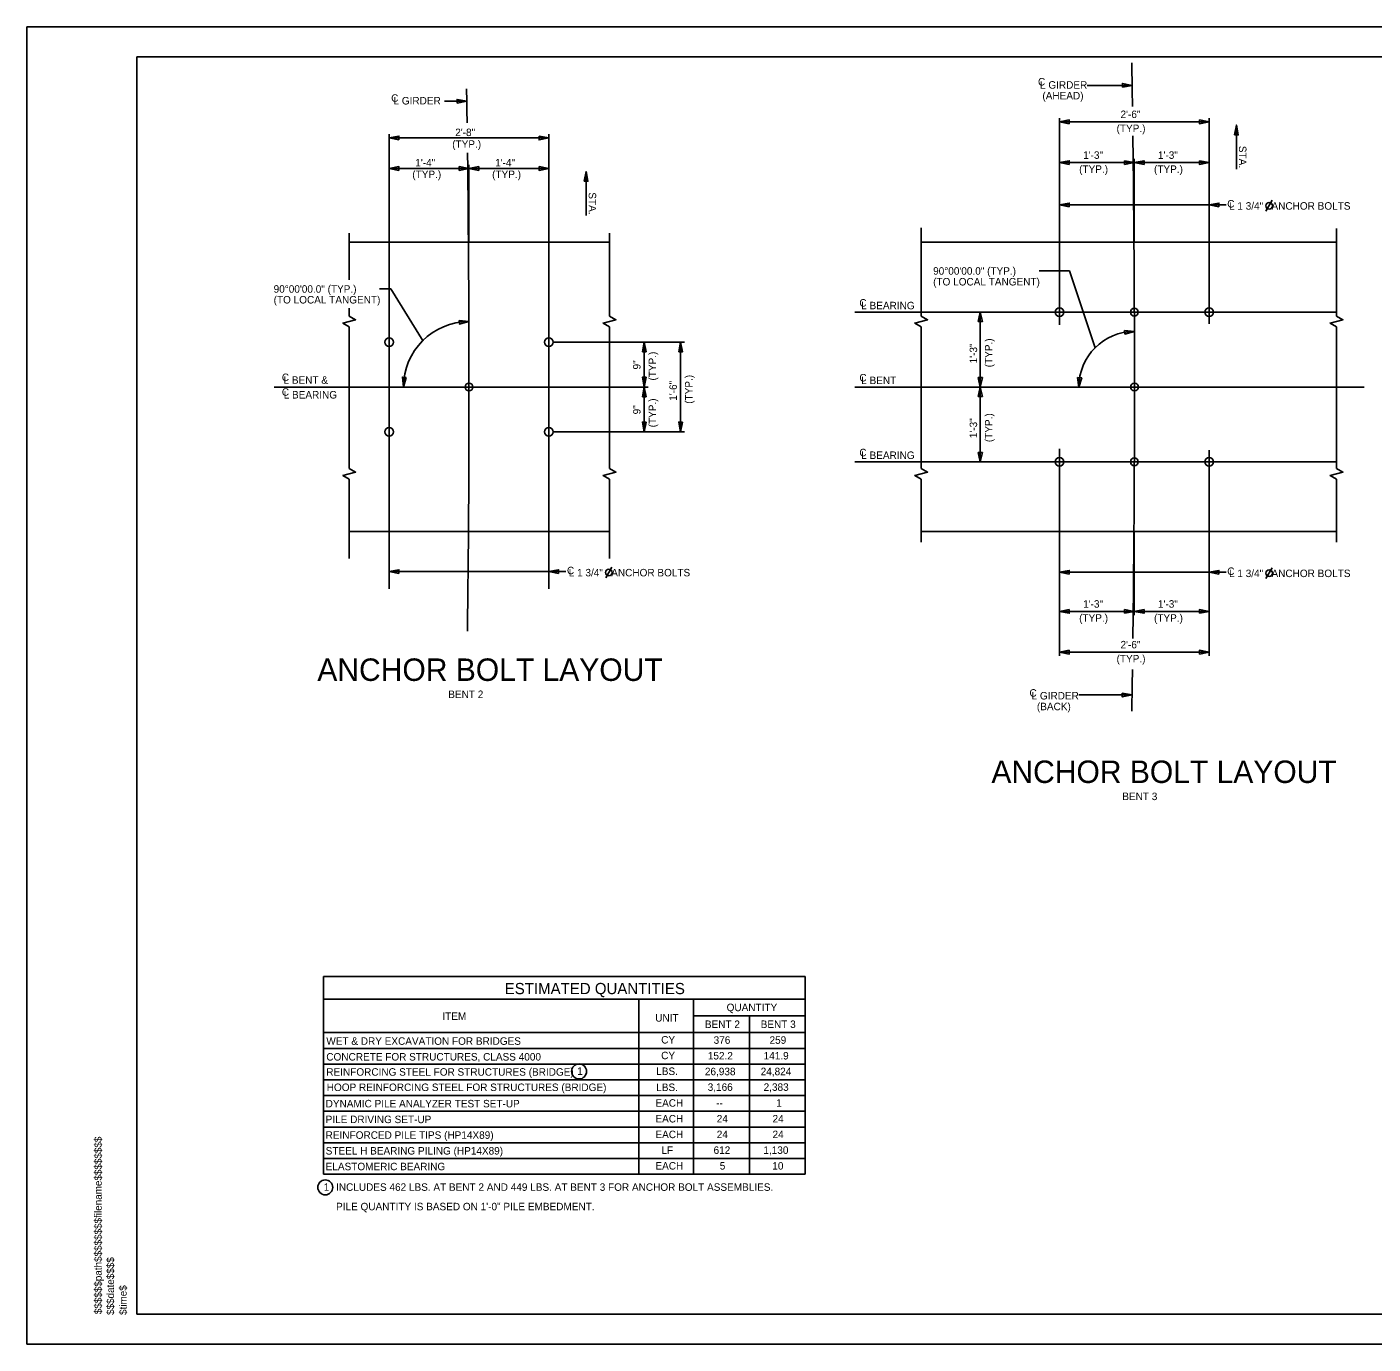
# Model space of a CAD drawing. Extents: x 1970675.2 to 1970711.3, y 796145.2 to 796167.2.
# Drawn here: x 1970675.24 to 1970697.72, y 796145.25 to 796167.25 of the extents above; entities that cross this region are included whole.
import ezdxf

# ---------------------------------------------------------------- set-up
doc = ezdxf.new("R2010")
doc.units = 0
for name, color, linetype in [('BR_AUTO DIMENSION', 7, 'Continuous'), ('BR_BORDER LINES', 7, 'Continuous'), ('BR_CENTER LINES', 7, 'Continuous'), ('BR_CONCRETE', 7, 'Continuous'), ('BR_STRUCTURAL STEEL', 7, 'Continuous'), ('BR_TEXT', 7, 'Continuous'), ('Default', 7, 'Continuous'), ('Level 31', 7, 'Continuous'), ('RD_SHT_ID', 7, 'Continuous')]:
    doc.layers.add(name, color=color, linetype=linetype)

msp = doc.modelspace()

# ---------------------------------------------------------------- linework, layer by layer
at = {"layer": 'BR_AUTO DIMENSION'}
for p, q in [((1970692.947, 796166.27), (1970693.696, 796166.27)), ((1970682.211, 796166.005), (1970682.584, 796166.005)), ((1970692.482, 796164.614), (1970692.482, 796165.724)), ((1970692.482, 796165.661), (1970694.982, 796165.661)), ((1970694.982, 796164.614), (1970694.982, 796165.724)), ((1970681.287, 796163.711), (1970681.287, 796165.454)), ((1970683.954, 796163.711), (1970683.954, 796165.454)), ((1970681.287, 796165.392), (1970683.954, 796165.392)), ((1970692.482, 796164.981), (1970693.732, 796164.981)), ((1970693.732, 796163.649), (1970693.732, 796165.043)), ((1970693.732, 796164.981), (1970694.982, 796164.981)), ((1970681.287, 796164.882), (1970682.62, 796164.882)), ((1970682.62, 796163.711), (1970682.62, 796164.944)), ((1970682.62, 796163.649), (1970682.62, 796164.944)), ((1970683.954, 796164.882), (1970682.62, 796164.882)), ((1970695.264, 796164.274), (1970692.482, 796164.274)), ((1970692.143, 796163.173), (1970692.649, 796163.173)), ((1970693.078, 796161.888), (1970692.649, 796163.173)), ((1970681.127, 796162.872), (1970681.316, 796162.872)), ((1970681.856, 796162), (1970681.316, 796162.872)), ((1970691.158, 796161.232), (1970691.158, 796162.482)), ((1970684.016, 796161.982), (1970686.217, 796161.982)), ((1970685.548, 796161.982), (1970685.548, 796161.232)), ((1970686.154, 796161.982), (1970686.154, 796160.482)), ((1970684.016, 796161.232), (1970685.61, 796161.232)), ((1970685.548, 796161.232), (1970685.548, 796160.482)), ((1970691.158, 796159.982), (1970691.158, 796161.232)), ((1970684.016, 796160.482), (1970686.217, 796160.482)), ((1970693.732, 796158.816), (1970693.732, 796157.421)), ((1970684.236, 796158.148), (1970681.287, 796158.148)), ((1970695.264, 796158.137), (1970692.482, 796158.137)), ((1970692.482, 796157.85), (1970692.482, 796156.741)), ((1970694.982, 796157.85), (1970694.982, 796156.741)), ((1970692.482, 796157.484), (1970693.732, 796157.484)), ((1970693.732, 796157.484), (1970694.982, 796157.484)), ((1970692.482, 796156.804), (1970694.982, 796156.804)), ((1970693.694, 796156.089), (1970692.808, 796156.089)), ((1970680.189, 796151.385), (1970688.235, 796151.385)), ((1970680.189, 796148.084), (1970680.189, 796151.385)), ((1970688.235, 796148.084), (1970688.235, 796151.385)), ((1970680.189, 796151.01), (1970688.235, 796151.01)), ((1970685.454, 796148.084), (1970685.454, 796151.01)), ((1970686.371, 796148.084), (1970686.371, 796151.01)), ((1970686.371, 796150.729), (1970688.235, 796150.729)), ((1970687.303, 796148.084), (1970687.303, 796150.729)), ((1970680.189, 796150.448), (1970688.235, 796150.448)), ((1970680.189, 796150.185), (1970688.235, 796150.185)), ((1970680.189, 796149.923), (1970688.235, 796149.923)), ((1970680.189, 796149.662), (1970688.235, 796149.662)), ((1970680.189, 796149.396), (1970688.235, 796149.396)), ((1970680.189, 796149.134), (1970688.235, 796149.134)), ((1970680.189, 796148.871), (1970688.235, 796148.871)), ((1970680.189, 796148.609), (1970688.235, 796148.609)), ((1970680.189, 796148.346), (1970688.235, 796148.346)), ((1970680.189, 796148.084), (1970688.235, 796148.084))]:
    msp.add_line(p, q, dxfattribs=at)
for points in [[(1970693.534, 796166.239), (1970693.696, 796166.27), (1970693.534, 796166.302)], [(1970682.421, 796165.974), (1970682.584, 796166.005), (1970682.421, 796166.036)], [(1970692.645, 796165.63), (1970692.482, 796165.661), (1970692.645, 796165.692)], [(1970694.82, 796165.692), (1970694.982, 796165.661), (1970694.82, 796165.63)], [(1970681.45, 796165.36), (1970681.287, 796165.392), (1970681.45, 796165.423)], [(1970683.791, 796165.423), (1970683.954, 796165.392), (1970683.791, 796165.36)], [(1970695.405, 796165.443), (1970695.437, 796165.606), (1970695.468, 796165.443)], [(1970692.645, 796164.949), (1970692.482, 796164.981), (1970692.645, 796165.012)], [(1970693.57, 796165.012), (1970693.732, 796164.981), (1970693.57, 796164.949)], [(1970693.895, 796164.949), (1970693.732, 796164.981), (1970693.895, 796165.012)], [(1970694.82, 796165.012), (1970694.982, 796164.981), (1970694.82, 796164.949)], [(1970681.45, 796164.85), (1970681.287, 796164.882), (1970681.45, 796164.913)], [(1970682.458, 796164.913), (1970682.62, 796164.882), (1970682.458, 796164.85)], [(1970682.783, 796164.85), (1970682.62, 796164.882), (1970682.783, 796164.913)], [(1970683.791, 796164.913), (1970683.954, 796164.882), (1970683.791, 796164.85)], [(1970684.544, 796164.668), (1970684.576, 796164.831), (1970684.607, 796164.668)], [(1970692.645, 796164.242), (1970692.482, 796164.274), (1970692.645, 796164.305)], [(1970695.145, 796164.242), (1970694.982, 796164.274), (1970695.145, 796164.305)], [(1970682.454, 796162.344), (1970682.619, 796162.326), (1970682.459, 796162.282)], [(1970691.122, 796162.326), (1970691.158, 796162.482), (1970691.194, 796162.326)], [(1970693.569, 796162.178), (1970693.733, 796162.161), (1970693.574, 796162.115)], [(1970685.516, 796161.82), (1970685.548, 796161.982), (1970685.579, 796161.82)], [(1970686.123, 796161.82), (1970686.154, 796161.982), (1970686.186, 796161.82)], [(1970681.57, 796161.392), (1970681.526, 796161.232), (1970681.507, 796161.397)], [(1970685.579, 796161.395), (1970685.548, 796161.232), (1970685.516, 796161.395)], [(1970691.122, 796161.388), (1970691.158, 796161.232), (1970691.194, 796161.388)], [(1970692.783, 796161.391), (1970692.806, 796161.232), (1970692.855, 796161.385)], [(1970685.516, 796161.07), (1970685.548, 796161.232), (1970685.579, 796161.07)], [(1970691.122, 796161.076), (1970691.158, 796161.232), (1970691.194, 796161.076)], [(1970685.579, 796160.645), (1970685.548, 796160.482), (1970685.516, 796160.645)], [(1970686.186, 796160.645), (1970686.154, 796160.482), (1970686.123, 796160.645)], [(1970691.122, 796160.138), (1970691.158, 796159.982), (1970691.194, 796160.138)], [(1970681.45, 796158.117), (1970681.287, 796158.148), (1970681.45, 796158.18)], [(1970684.116, 796158.117), (1970683.954, 796158.148), (1970684.116, 796158.18)], [(1970692.645, 796158.105), (1970692.482, 796158.137), (1970692.645, 796158.168)], [(1970695.145, 796158.105), (1970694.982, 796158.137), (1970695.145, 796158.168)], [(1970692.645, 796157.515), (1970692.482, 796157.484), (1970692.645, 796157.453)], [(1970693.57, 796157.453), (1970693.732, 796157.484), (1970693.57, 796157.515)], [(1970693.895, 796157.515), (1970693.732, 796157.484), (1970693.895, 796157.453)], [(1970694.82, 796157.453), (1970694.982, 796157.484), (1970694.82, 796157.515)], [(1970692.645, 796156.835), (1970692.482, 796156.804), (1970692.645, 796156.772)], [(1970694.82, 796156.772), (1970694.982, 796156.804), (1970694.82, 796156.835)], [(1970693.532, 796156.12), (1970693.694, 796156.089), (1970693.532, 796156.057)]]:
    msp.add_lwpolyline(points, close=True, dxfattribs=at)
for centre in [(1970693.732, 796162.482), (1970682.62, 796161.232), (1970693.735, 796161.232), (1970693.732, 796159.982)]:
    msp.add_circle(centre, 0.0652, dxfattribs=at)
for centre, radius, start in [((1970682.62, 796161.232), 1.094, 90.1013), ((1970693.735, 796161.232), 0.929, 90.081)]:
    msp.add_arc(centre, radius, start, 180, dxfattribs=at)
at = {"layer": 'BR_BORDER LINES'}
for p, q in [((1970710.736, 796166.746), (1970677.07, 796166.746)), ((1970677.07, 796145.746), (1970677.07, 796166.746)), ((1970677.07, 796145.746), (1970710.736, 796145.746))]:
    msp.add_line(p, q, dxfattribs=at)
at = {"layer": 'BR_CENTER LINES'}
for p, q in [((1970692.482, 796162.268), (1970692.482, 796164.614)), ((1970694.982, 796162.286), (1970694.982, 796164.614)), ((1970681.287, 796157.861), (1970681.287, 796164.082)), ((1970683.954, 796157.861), (1970683.954, 796163.98)), ((1970697.111, 796162.482), (1970689.064, 796162.482)), ((1970684.968, 796161.232), (1970679.364, 796161.232)), ((1970697.57, 796161.232), (1970689.064, 796161.232)), ((1970692.482, 796160.197), (1970692.482, 796157.85)), ((1970694.982, 796160.178), (1970694.982, 796157.85)), ((1970697.111, 796159.982), (1970689.064, 796159.982))]:
    msp.add_line(p, q, dxfattribs=at)
for centre, radius, start, end in [((1970365.235, 796161.232), 328.5, 0.81737, 0.9448), ((1970373.12, 796161.232), 309.5, 0.81693, 0.92238), ((1970365.235, 796161.232), 328.5, 360, 0.73157), ((1970373.12, 796161.232), 309.5, 359.24506, 0.72377), ((1970365.235, 796161.232), 328.5, 359.26762, 360), ((1970365.235, 796161.232), 328.5, 359.0552, 359.17682)]:
    msp.add_arc(centre, radius, start, end, dxfattribs=at)
at = {"layer": 'BR_CONCRETE'}
for p, q in [((1970684.968, 796163.649), (1970680.621, 796163.649)), ((1970697.111, 796163.649), (1970690.173, 796163.649)), ((1970690.173, 796161.232), (1970697.111, 796161.232)), ((1970684.968, 796158.816), (1970680.621, 796158.816)), ((1970697.111, 796158.816), (1970690.173, 796158.816))]:
    msp.add_line(p, q, dxfattribs=at)
at = {"layer": 'BR_STRUCTURAL STEEL'}
for centre, radius in [((1970692.482, 796162.482), 0.073), ((1970694.982, 796162.482), 0.073), ((1970681.287, 796161.982), 0.073), ((1970683.954, 796161.982), 0.0729), ((1970681.287, 796160.482), 0.073), ((1970683.954, 796160.482), 0.073), ((1970692.482, 796159.982), 0.073), ((1970694.982, 796159.982), 0.073)]:
    msp.add_circle(centre, radius, dxfattribs=at)
at = {"layer": 'BR_TEXT'}
for p, q in [((1970695.437, 796164.873), (1970695.437, 796165.606)), ((1970684.576, 796164.098), (1970684.576, 796164.831)), ((1970695.931, 796164.169), (1970696.036, 796164.35)), ((1970684.903, 796158.043), (1970685.008, 796158.225)), ((1970695.931, 796158.032), (1970696.036, 796158.213))]:
    msp.add_line(p, q, dxfattribs=at)
for centre, radius in [((1970695.984, 796164.259), 0.055), ((1970684.955, 796158.134), 0.055), ((1970695.984, 796158.122), 0.055), ((1970684.459, 796149.8), 0.125), ((1970680.219, 796147.864), 0.125)]:
    msp.add_circle(centre, radius, dxfattribs=at)
at = {"layer": 'Default'}
for p, q in [((1970690.173, 796163.888), (1970690.173, 796162.417)), ((1970697.111, 796163.878), (1970697.111, 796162.417)), ((1970680.621, 796163.803), (1970680.621, 796163.023)), ((1970684.968, 796163.803), (1970684.968, 796162.417)), ((1970680.621, 796162.547), (1970680.621, 796162.417)), ((1970680.621, 796162.239), (1970680.621, 796161.232)), ((1970684.968, 796162.239), (1970684.968, 796161.232)), ((1970690.173, 796162.239), (1970690.173, 796161.232)), ((1970697.111, 796162.239), (1970697.111, 796161.232)), ((1970680.621, 796161.232), (1970680.621, 796159.871)), ((1970684.968, 796161.232), (1970684.968, 796159.871)), ((1970690.173, 796161.232), (1970690.173, 796159.871)), ((1970697.111, 796161.232), (1970697.111, 796159.871)), ((1970680.621, 796159.693), (1970680.621, 796158.366)), ((1970684.968, 796159.693), (1970684.968, 796158.366)), ((1970690.173, 796159.693), (1970690.173, 796158.639)), ((1970697.111, 796159.693), (1970697.111, 796158.639))]:
    msp.add_line(p, q, dxfattribs=at)
for points in [[(1970680.621, 796162.239), (1970680.513, 796162.301), (1970680.726, 796162.356), (1970680.621, 796162.417)], [(1970684.968, 796162.239), (1970684.86, 796162.301), (1970685.073, 796162.356), (1970684.968, 796162.417)], [(1970690.173, 796162.239), (1970690.065, 796162.301), (1970690.278, 796162.356), (1970690.173, 796162.417)], [(1970697.111, 796162.239), (1970697.003, 796162.301), (1970697.216, 796162.356), (1970697.111, 796162.417)], [(1970680.621, 796159.693), (1970680.513, 796159.755), (1970680.726, 796159.81), (1970680.621, 796159.871)], [(1970684.968, 796159.693), (1970684.86, 796159.755), (1970685.073, 796159.81), (1970684.968, 796159.871)], [(1970690.173, 796159.693), (1970690.065, 796159.755), (1970690.278, 796159.81), (1970690.173, 796159.871)], [(1970697.111, 796159.693), (1970697.003, 796159.755), (1970697.216, 796159.81), (1970697.111, 796159.871)]]:
    msp.add_lwpolyline(points, dxfattribs=at)
at = {"layer": 'Level 31'}
msp.add_line((1970711.236, 796167.246), (1970675.236, 796167.246), dxfattribs=at)
msp.add_lwpolyline([(1970675.236, 796167.246), (1970675.236, 796145.246), (1970711.236, 796145.246), (1970711.236, 796167.246)], dxfattribs=at)

# ---------------------------------------------------------------- texts
at = {"layer": 'BR_AUTO DIMENSION'}
for s, rotation, p in [('C', 360, (1970692.123, 796166.268)), ('L GIRDER', 360, (1970692.157, 796166.215)), ('C', 360, (1970681.32, 796165.996)), ('(AHEAD)', 360, (1970692.197, 796166.035)), ('L GIRDER', 360, (1970681.359, 796165.951)), ('STA.', 270, (1970695.48, 796165.259)), ('STA.', 270, (1970684.619, 796164.484)), ('C', 360, (1970695.284, 796164.23)), ('L 1 3/4"   ANCHOR BOLTS', 360, (1970695.314, 796164.194)), ('C', 360, (1970689.14, 796162.575)), ('L BEARING', 360, (1970689.171, 796162.53)), ('9"', 90, (1970685.485, 796161.525)), ('(TYP.)', 90, (1970685.746, 796161.34)), ('C', 360, (1970679.494, 796161.331)), ('L BENT &', 360, (1970679.522, 796161.286)), ('(TYP.)', 90, (1970686.353, 796160.952)), ('C', 360, (1970689.14, 796161.325)), ('L BENT', 360, (1970689.171, 796161.28)), ('C', 360, (1970679.494, 796161.086)), ('L BEARING', 360, (1970679.525, 796161.04)), ('1\'-6"', 90, (1970686.092, 796161.002)), ('9"', 90, (1970685.485, 796160.775)), ('(TYP.)', 90, (1970685.746, 796160.558)), ('C', 360, (1970689.14, 796160.075)), ('L BEARING', 360, (1970689.171, 796160.03)), ('C', 360, (1970684.256, 796158.105)), ('C', 360, (1970695.284, 796158.093)), ('L 1 3/4"   ANCHOR BOLTS', 360, (1970684.286, 796158.069)), ('L 1 3/4"   ANCHOR BOLTS', 360, (1970695.314, 796158.057)), ('BENT 2', 360, (1970682.274, 796156.037)), ('C', 360, (1970691.981, 796156.06)), ('L GIRDER', 360, (1970692.016, 796156.013)), ('(BACK)', 360, (1970692.105, 796155.833)), ('BENT 3', 360, (1970693.532, 796154.332))]:
    msp.add_text(s, height=0.125, rotation=rotation, dxfattribs=at).set_placement(p)
for s, p in [('2\'-6"', (1970693.502, 796165.724)), ('2\'-8"', (1970682.39, 796165.423)), ('(TYP.)', (1970693.436, 796165.489)), ('(TYP.)', (1970682.34, 796165.227)), ('1\'-4"', (1970681.723, 796164.916)), ('1\'-4"', (1970683.056, 796164.916)), ('1\'-3"', (1970692.877, 796165.043)), ('1\'-3"', (1970694.127, 796165.043)), ('(TYP.)', (1970681.673, 796164.722)), ('(TYP.)', (1970683.006, 796164.722)), ('(TYP.)', (1970692.811, 796164.809)), ('(TYP.)', (1970694.061, 796164.809)), ('90%%D00\'00.0" (TYP.)', (1970690.372, 796163.108)), ('(TO LOCAL TANGENT)', (1970690.372, 796162.928)), ('90%%D00\'00.0" (TYP.)', (1970679.357, 796162.807)), ('(TO LOCAL TANGENT)', (1970679.357, 796162.627)), ('1\'-3"', (1970692.877, 796157.546)), ('1\'-3"', (1970694.127, 796157.546)), ('(TYP.)', (1970692.811, 796157.312)), ('(TYP.)', (1970694.061, 796157.312)), ('2\'-6"', (1970693.502, 796156.866)), ('(TYP.)', (1970693.436, 796156.631))]:
    msp.add_text(s, height=0.125, dxfattribs=at).set_placement(p)
at = {"layer": 'BR_TEXT'}
for s, height, rotation, p in [('1\'-3"', 0.125, 90, (1970691.107, 796161.627)), ('(TYP.)', 0.125, 90, (1970691.363, 796161.561)), ('1\'-3"', 0.125, 90, (1970691.107, 796160.377)), ('(TYP.)', 0.125, 90, (1970691.363, 796160.311)), ('ANCHOR BOLT LAYOUT', 0.375, 360, (1970680.087, 796156.323)), ('ANCHOR BOLT LAYOUT', 0.375, 360, (1970691.345, 796154.618)), ('ESTIMATED QUANTITIES', 0.1875, 0, (1970683.217, 796151.091)), ('QUANTITY', 0.125, 0, (1970686.923, 796150.807)), ('ITEM', 0.125, 0, (1970682.176, 796150.661)), ('UNIT', 0.125, 0, (1970685.73, 796150.632)), ('BENT 2', 0.125, 0, (1970686.56, 796150.526)), ('BENT 3', 0.125, 0, (1970687.492, 796150.526)), ('WET & DRY EXCAVATION FOR BRIDGES', 0.125, 0, (1970680.237, 796150.245)), ('CY', 0.125, 0, (1970685.83, 796150.266)), ('376', 0.125, 0, (1970686.706, 796150.262)), ('259', 0.125, 0, (1970687.64, 796150.262)), ('CY', 0.125, 0, (1970685.83, 796150.004)), ('152.2', 0.125, 0, (1970686.609, 796150)), ('141.9', 0.125, 0, (1970687.541, 796150)), ('CONCRETE FOR STRUCTURES, CLASS 4000', 0.125, 0, (1970680.237, 796149.982)), ('REINFORCING STEEL FOR STRUCTURES (BRIDGE)', 0.125, 0, (1970680.237, 796149.729)), ('1', 0.125, 0, (1970684.426, 796149.743)), ('LBS.', 0.125, 0, (1970685.747, 796149.741)), ('26,938', 0.125, 0, (1970686.56, 796149.737)), ('24,824', 0.125, 0, (1970687.492, 796149.737)), ('HOOP REINFORCING STEEL FOR STRUCTURES (BRIDGE)', 0.125, 0, (1970680.244, 796149.473)), ('LBS.', 0.125, 0, (1970685.747, 796149.473)), ('3,166', 0.125, 0, (1970686.607, 796149.476)), ('2,383', 0.125, 0, (1970687.541, 796149.476)), ('DYNAMIC PILE ANALYZER TEST SET-UP', 0.125, 0, (1970680.226, 796149.2)), ('EACH', 0.125, 0, (1970685.734, 796149.211)), ('--', 0.125, 0, (1970686.75, 796149.211)), ('1', 0.125, 0, (1970687.752, 796149.211)), ('PILE DRIVING SET-UP', 0.125, 0, (1970680.226, 796148.937)), ('EACH', 0.125, 0, (1970685.734, 796148.948)), ('24', 0.125, 0, (1970686.758, 796148.948)), ('24', 0.125, 0, (1970687.69, 796148.948)), ('REINFORCED PILE TIPS (HP14X89)', 0.125, 0, (1970680.226, 796148.675)), ('EACH', 0.125, 0, (1970685.734, 796148.686)), ('24', 0.125, 0, (1970686.758, 796148.686)), ('24', 0.125, 0, (1970687.69, 796148.686)), ('STEEL H BEARING PILING (HP14X89)', 0.125, 0, (1970680.226, 796148.412)), ('LF', 0.125, 0, (1970685.834, 796148.423)), ('612', 0.125, 0, (1970686.705, 796148.423)), ('1,130', 0.125, 0, (1970687.537, 796148.423)), ('ELASTOMERIC BEARING', 0.125, 0, (1970680.226, 796148.15)), ('EACH', 0.125, 0, (1970685.734, 796148.161)), ('5', 0.125, 0, (1970686.808, 796148.161)), ('10', 0.125, 0, (1970687.686, 796148.161)), ('1', 0.125, 360, (1970680.194, 796147.807)), ('INCLUDES 462 LBS. AT BENT 2 AND 449 LBS. AT BENT 3 FOR ANCHOR BOLT ASSEMBLIES.', 0.125, 360, (1970680.4, 796147.806)), ('PILE QUANTITY IS BASED ON 1\'-0" PILE EMBEDMENT.', 0.125, 360, (1970680.4, 796147.481))]:
    msp.add_text(s, height=height, rotation=rotation, dxfattribs=at).set_placement(p)
at = {"layer": 'RD_SHT_ID'}
for s, height, p in [('$$$$$$path$$$$$$$$filename$$$$$$$$', 0.12347, (1970676.486, 796145.746)), ('$$$date$$$$', 0.12347, (1970676.692, 796145.733)), ('$time$', 0.1235, (1970676.903, 796145.733))]:
    msp.add_text(s, height=height, rotation=90, dxfattribs=at).set_placement(p)

doc.saveas('drawing.dxf')
